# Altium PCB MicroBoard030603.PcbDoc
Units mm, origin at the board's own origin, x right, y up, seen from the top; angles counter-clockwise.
Board outline 99.8 x 61.6 mm, 2 copper layers (Top Layer, Bottom Layer); 74 components, 76 nets, 326 pads, 104 vias.
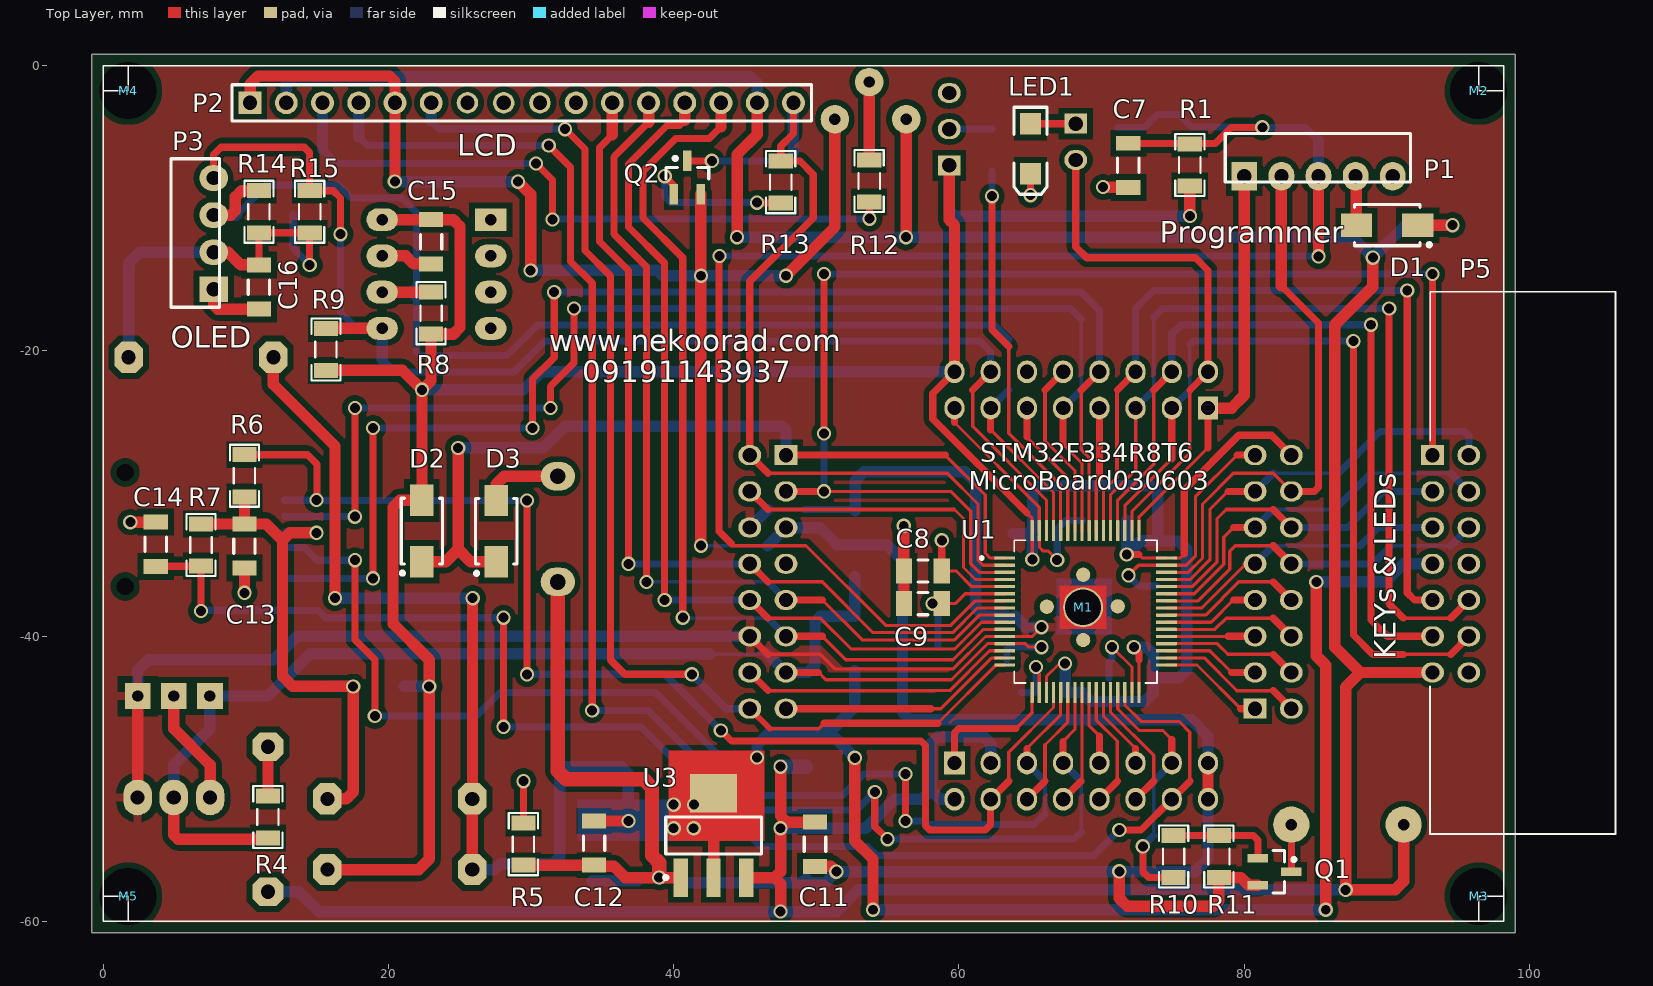
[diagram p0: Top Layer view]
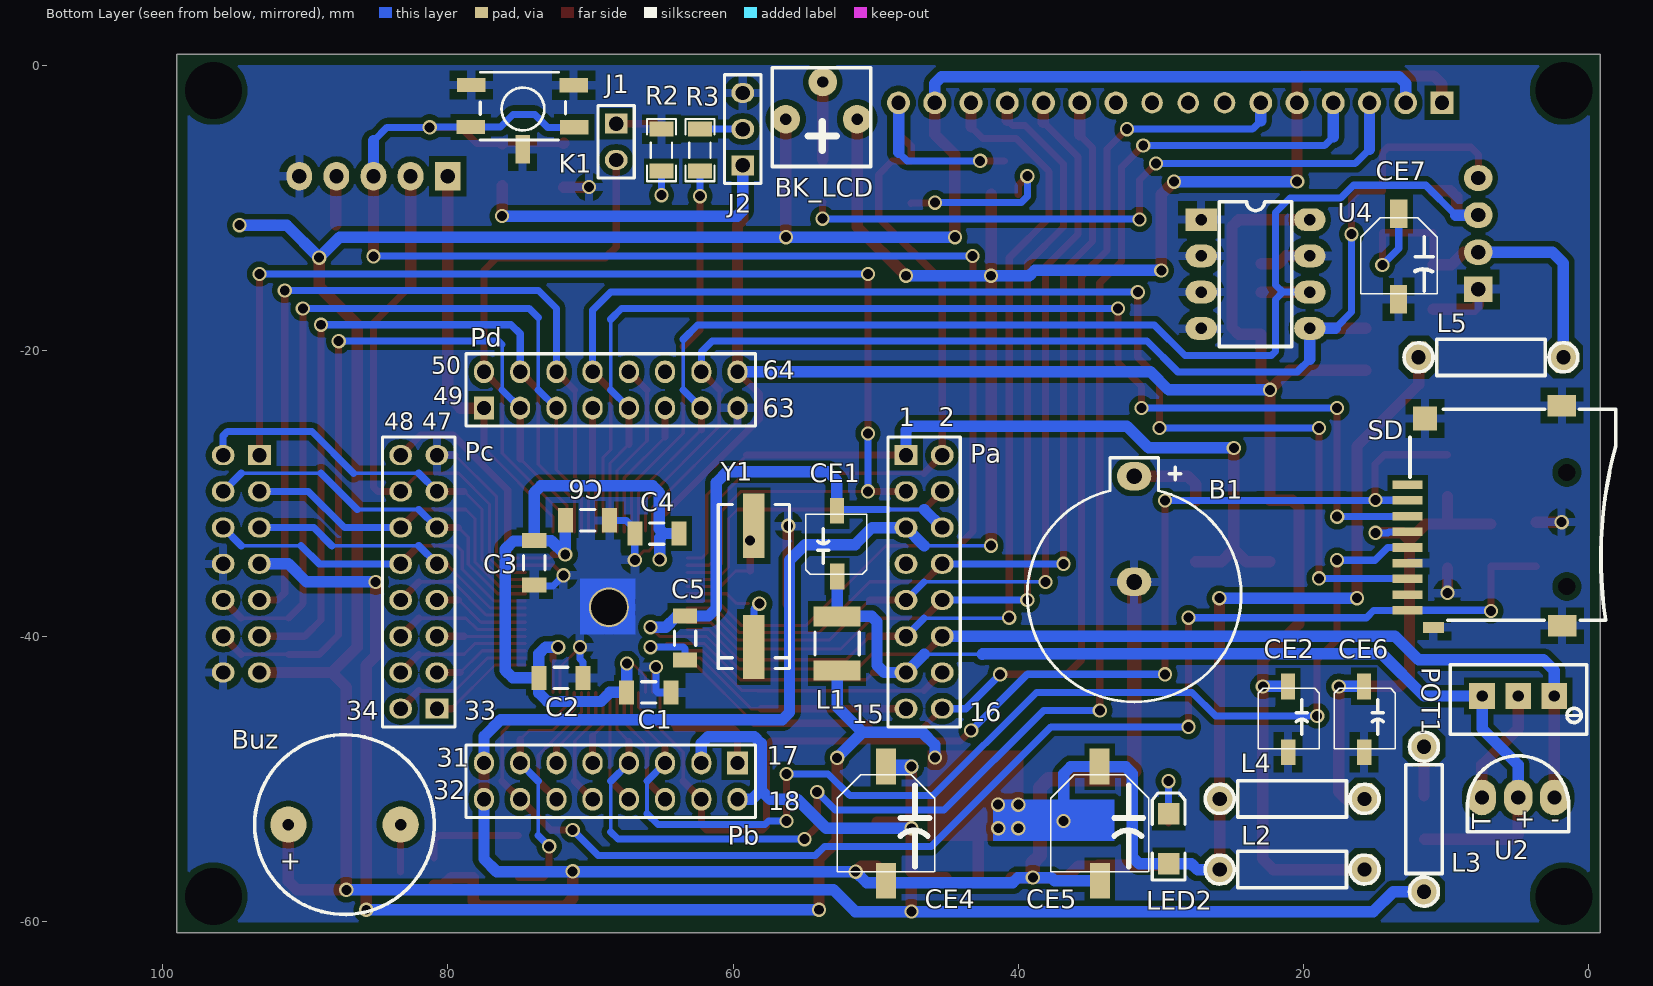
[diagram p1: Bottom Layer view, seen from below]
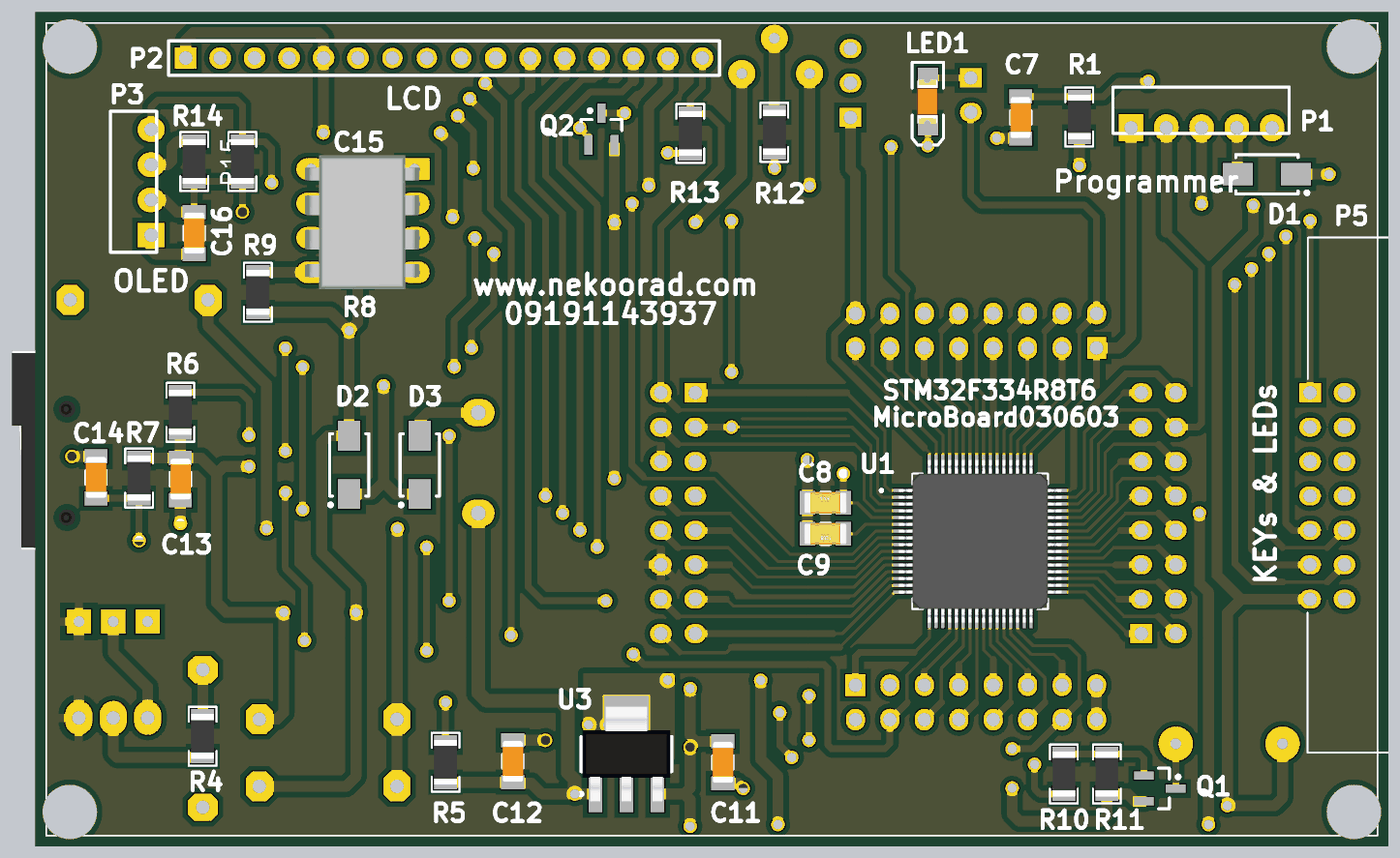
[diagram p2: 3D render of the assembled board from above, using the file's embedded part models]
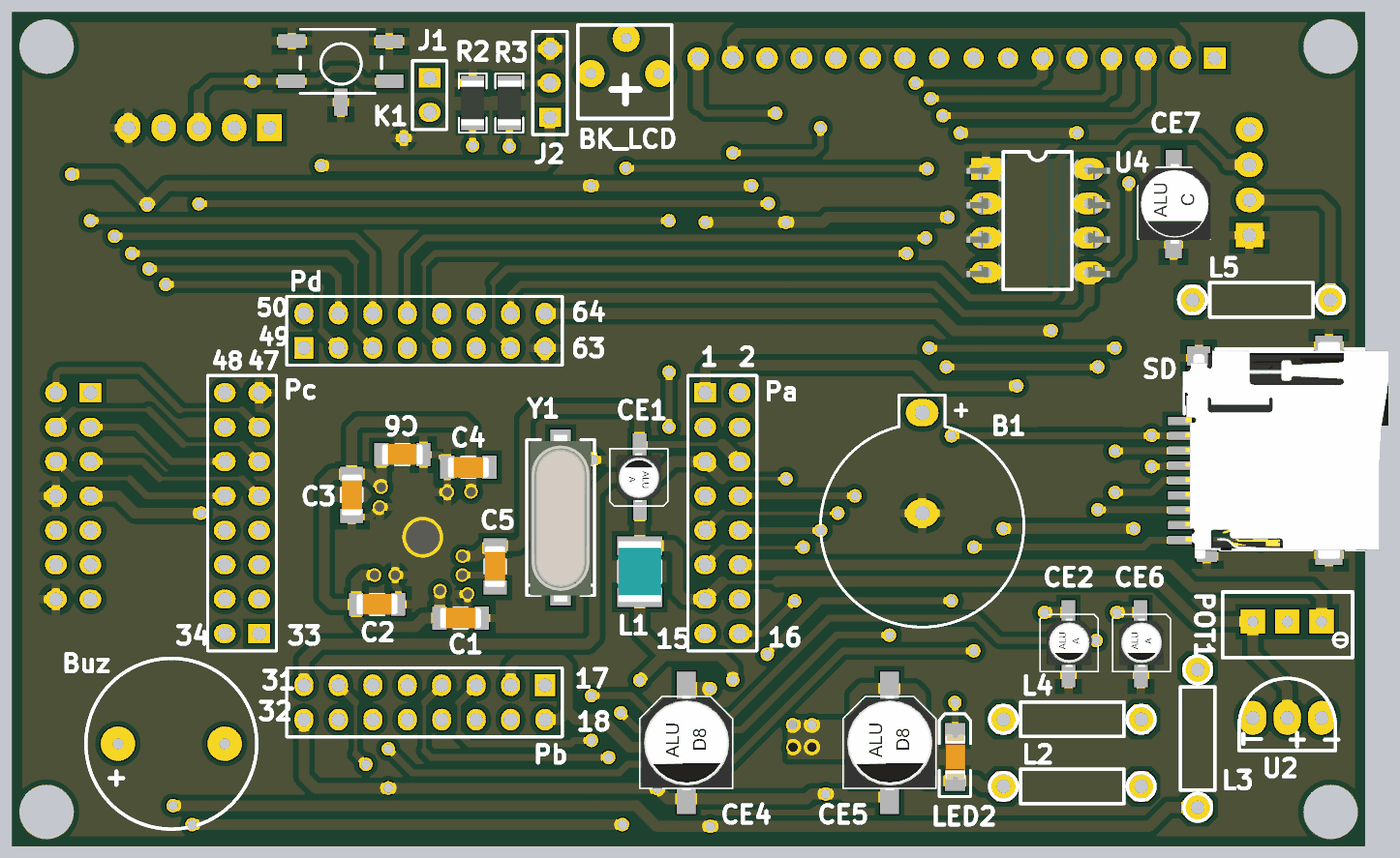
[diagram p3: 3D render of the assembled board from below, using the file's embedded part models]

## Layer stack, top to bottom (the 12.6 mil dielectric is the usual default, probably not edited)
Top Solder: solder mask 0.0102, Solder Resist, Dk 3.5
Top Layer: signal copper 0.0356
Dielectric 1: dielectric 0.32, FR-4, Dk 4.8
Bottom Layer: signal copper 0.0356
Bottom Solder: solder mask 0.0102, Solder Resist, Dk 3.5

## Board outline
-0.8,-60.8 -0.8,0.8 99,0.8 99,-60.8

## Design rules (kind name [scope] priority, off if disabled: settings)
Clearance Clearance_2 [InNamedPolygon('Bottom Layer-GND')] p1: gap=0.254 ignorepadtopadclearanceinfootprint=FALSE except(0: Arc-Hole Track-Hole SMDPad-Hole THPad-Hole Via-Hole Fill-Hole Poly-Hole Region-Hole Text-Hole)
Clearance Clearance_1 [InNamedPolygon('Bottom Layer-GND')] p2: gap=0.254 ignorepadtopadclearanceinfootprint=FALSE except(0: Arc-Hole Track-Hole SMDPad-Hole THPad-Hole Via-Hole Fill-Hole Poly-Hole Region-Hole Text-Hole)
Clearance [All] p3: gap=0.4 ignorepadtopadclearanceinfootprint=FALSE
PlaneClearance [All] p1: clearance=0.5
PlaneConnect [All] p1: planeconnectstyle=Relief reliefexpansion=0.508 reliefentries=4 reliefconductorwidth=0.6 reliefairgap=0.5
PolygonConnect [All] p1: connectstyle=Relief reliefconductorwidth=0.6 reliefentries=4 polygonreliefangle="90 Angle" airgapwidth=0.5
RoutingVias [All] p1: holewidth=0.711 width=1.27 viastyle="Through Hole" minholewidth=0.711 minwidth=1.27 maxholewidth=0.711 maxwidth=1.27
SolderMaskExpansion [All] p1: expansion=0.102 istentingtop=FALSE
Width [All] p1: maxlimit=1 minlimit=0.2 preferedwidth=0.5 minimp=50.000000 maximp=50.000000 favimp=50.000000
28 further rules are at their usual default settings.

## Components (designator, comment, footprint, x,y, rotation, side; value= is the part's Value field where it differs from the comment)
B1 "CR1220 Holder" "BAT S" 31.877,-28.778 r0 bottom
BK_LCD "10K" POT-Blue 56.298,-3.759 r180 bottom
Buz "BUZZER" BUZ 87.249,-53.213 r0 bottom
C1 "Comment" SMD_CAP_1206. 65.913,-43.942 r0 bottom
C2 "Comment" SMD_CAP_1206. 72.068,-42.927 r0 bottom
C3 "Comment" SMD_CAP_1206. 73.946,-34.849 r90 bottom
C4 "Comment" SMD_CAP_1206. 65.346,-32.8 r180 bottom
C5 "Comment" SMD_CAP_1206. 63.373,-40.132 r270 bottom
C6 "Comment" SMD_CAP_1206. 70.206,-31.877 r0 bottom
C7 "Comment" SMD_CAP_1206. 71.882,-6.985 r270 top
C8 "Comment" "CAP 1206 (3216X15L)" 57.476,-35.433 r0 top
C9 "Comment" "CAP 1206 (3216X15L)" 57.476,-37.719 r180 top
C11 "Comment" SMD_CAP_1206. 49.911,-54.585 r90 top
C12 "Comment" SMD_CAP_1206. 34.417,-54.508 r90 top
C13 "Comment" SMD_CAP_1206. 9.906,-33.68 r90 top
C14 "Comment" SMD_CAP_1206. 3.683,-33.553 r90 top
C15 "Comment" SMD_CAP_1206. 22.987,-12.344 r90 top
C16 "Comment" SMD_CAP_1206. 10.922,-15.519 r90 top
CE1 "10uf tantal" cap-e-2 52.795,-32.424 r0 bottom
CE2 "10uf tantal" cap-e-2 21.007,-46.913 r180 bottom
CE4 "100uF" cap-e-4 49.276,-55.44 r180 bottom
CE5 "100uF" cap-e-4 34.29,-55.44 r180 bottom
CE6 "10uf tantal" cap-e-2 15.673,-46.913 r180 bottom
CE7 "47uf tantal" CAP-E-3 13.26,-15.283 r180 bottom
D1 "SS12" "Diode SMA-M" 90.034,-11.176 r180 top
D2 "SS12" "Diode SMA-M" 22.352,-32.63 r90 top
D3 "SS12" "Diode SMA-M" 27.559,-32.639 r90 top
J1 "HDRM2" HDR1X2 68.199,-4.064 r270 bottom
J2 "HDRM3" HDR1X3 59.324,-6.985 r90 bottom
K1 "Push Button" "SW PB SMD" 78.359,-4.318 r180 bottom
L1 "Comment" INDC4532 52.705,-40.508 r270 bottom
L2 "Comment" "L RES" 25.908,-56.388 r180 bottom
L3 "Comment" "L RES" 11.532,-57.937 r90 bottom
L4 "Comment" "L RES" 25.908,-51.435 r180 bottom
L5 "Comment" "L RES" 11.963,-20.472 r180 bottom
LED1 "HB" LED_SMD_1206 62.803,-5.908 r270 top
LED2 "HB" LED_SMD_1206 27.243,-54.107 r90 bottom
M1 "Comment" Stud-hole#1 68.707,-37.973 r0 top value=DNP/MH
M2 "Comment" Stud-hole#2 96.45,-1.75 r0 top value=DNP/MH
M3 "Comment" Stud-hole#2 96.45,-58.25 r0 top value=DNP/MH
M4 "Comment" Stud-hole#2 1.75,-1.75 r0 top value=DNP/MH
M5 "Comment" Stud-hole#3 1.75,-58.25 r0 top value=DNP/MH
P1 "Programmer" "SIP 5 right" 90.431,-7.772 r270 top
P2 "LCD" HDR1X16 10.3,-2.6 r0 top
P3 "OLED" "sip 4 right" 7.747,-7.849 r0 top
P5 "Key LED" "IDC14 r lock" 93.243,-27.305 r270 top
Pa "Header 8X2" HDR2X8#1 47.879,-27.305 r270 bottom
Pb "Header 8X2" HDR2X8#2 59.69,-48.895 r0 bottom
Pc "Header 8X2" HDR2X8#1 80.772,-45.085 r90 bottom
Pd "Header 8X2" HDR2X8#1 77.47,-24.003 r180 bottom
POT1 "10K" "pot multi turn" 2.423,-44.196 r90 bottom
Q1 "BCV47" SOT23_M 82.137,-56.515 r0 top
Q2 "BCV47" SOT23_M 40.96,-7.842 r90 top
R1 "4K7" RES_1206 75.311,-6.985 r270 top
R2 "1K" RES_1206 65.905,-5.956 r270 bottom
R3 "100K" RES_1206 61.443,-5.884 r90 bottom
R4 "220" RES_1206 10.668,-52.705 r270 top
R5 "1K" RES_1206 30.345,-54.547 r90 top
R6 "4K7" RES_1206 9.025,-28.787 r270 top
R7 "10K" RES_1206 5.977,-33.642 r270 top
R8 "4K7" RES_1206 22.106,-17.386 r270 top
R9 "4K7" RES_1206 14.74,-19.926 r270 top
R10 "10K" RES_1206 74.176,-55.486 r270 top
R11 "10K" RES_1206 79.113,-55.414 r90 top
R12 "1K" RES_1206 54.588,-8.043 r90 top
R13 "10K" RES_1206 48.387,-8.128 r90 top
R14 "10K" RES_1206 10.041,-10.274 r270 top
R15 "10K" RES_1206 13.597,-10.274 r270 top
SD "Comment" "Micro sd csrd" 5.051,-31.213 r180 bottom
U1 "STM32F334R8T6" STM32F334R8T6 61.587,-34.522 r0 top
U2 "LM336" LM336 2.413,-51.308 r90 bottom
U3 "Comment" MP04A_M 42.799,-53.975 r90 top value=AMS1117-3.3V
U4 "EEPROM_I2C" dip8 27.178,-10.795 r180 bottom
Y1 "8Mhz" "Crystal SMD" 58.623,-36.234 r180 bottom

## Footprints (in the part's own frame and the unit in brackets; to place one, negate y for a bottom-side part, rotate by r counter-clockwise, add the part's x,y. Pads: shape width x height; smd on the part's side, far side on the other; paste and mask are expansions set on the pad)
"BAT S" [mm]
  oval 2.4x2 hole 1.1: 1(0,0) 2(0,7.417)
  silkscreen extent -7.5,-1.29 7.5,15.83
BUZ [mm]
  round 2.54 hole 0.8: 1(3.937,0) 2(-3.937,0)
  silkscreen extent -6.3,-6.3 6.3,6.3
"CAP 1206 (3216X15L)" [mm] "Chip Capacitor, 2-Leads, Body 3.2x1.6mm, IPC High Density"
  rect 1.15x1.75 smd: 1(-1.325,0) 2(1.325,0)
  silkscreen extent -0.35,-0.77 0.35,0.77, body extent -1.6,-0.8 1.6,0.8, height 1
cap-e-2 [mm] "1u-50v"
  rect 1x1.8 smd: 1(-0.09,3.39) 2(-0.075,-1.22)
  silkscreen extent -2.17,-0.98 2.11,3.25, body extent -1.68,-0.65 1.62,2.95, height 5.4
CAP-E-3 [mm] "22u-35v"
  rect 1.2x2 smd: 1(-0.065,4.9) 2(-0.075,-1.1)
  silkscreen extent -2.72,-0.69 2.62,4.62, body extent -2.64,-1.03 2.66,4.87, height 5.41
cap-e-4 [mm] "(100u-35v)(47u-16v)(220u-16v)(100u-16v)(10u-50v)"
  rect 1.4x2.5 smd: 1(-0.005,6.3) 2(0,-1.71)
  silkscreen extent -3.43,-1.07 3.43,5.71, body extent -3.27,-1.22 3.33,5.78, height 7.7
"Crystal SMD" [mm]
  rect 1.5x4.5 smd: 1(0.076,-4.524) 2(0.076,3.976)
  silkscreen extent -2.42,-6.02 2.58,5.48, body extent -2.17,-6.48 2.33,5.82, height 5.18
"Diode SMA-M" [mm] "Molded Diode, 2-Leads, Body 4.30x2.70mm, IPC Low Density"
  rect 2.2x1.65 smd: 1(2.15,0) 2(-2.15,0)
  silkscreen extent -3.08,-1.45 2.3,1.5, body extent -2.3,-1.45 2.3,1.45, height 2.44
dip8 [mm]
  rect 2.2x1.6 hole 0.8: 1(0,0)
  oval 2.2x1.6 hole 0.8: 2(0,-2.54) 3(0,-5.08) 4(0,-7.62) 5(7.62,-7.62) 6(7.62,-5.08) 7(7.62,-2.54) 8(7.62,0)
  silkscreen extent 1.27,-8.89 6.35,1.27, body extent -1.42,-8.88 9.14,1.02, height 3.75
HDR1X2 [mm] "Connector; Header; 2 Position"
  rect 1.4x1.6 hole 1: 1(0,0)
  oval 1.4x1.6 hole 1: 2(2.54,0)
  silkscreen extent -1.27,-1.27 3.81,1.27
HDR1X3 [mm] "Connector; Header; 3 Position"
  rect 1.4x1.6 hole 1: 1(0,0)
  oval 1.4x1.6 hole 1: 2(2.54,0) 3(5.08,0)
  silkscreen extent -1.27,-1.27 6.35,1.27
HDR1X16 [mm] "Connector; Header; 16 Position"
  rect 1.6x1.6 hole 1: 1(0,0)
  round 1.6 hole 1: 2(2.54,0) 3(5.08,0) 4(7.62,0) 5(10.16,0) 6(12.7,0) 10(22.86,0) 11(25.4,0) 12(27.94,0) 13(30.48,0) 14(33.02,0) 15(35.56,0) 16(38.1,0)
  round 1.5 hole 1: 7(15.24,0) 8(17.78,0) 9(20.32,0)
  silkscreen extent -1.27,-1.27 39.37,1.27
HDR2X8#1 [mm] "Connector; Header; 8x2 Position"
  rect 1.4x1.6 hole 1: 1(0,0)
  oval 1.4x1.6 hole 1: 2(0,2.54) 3(2.54,0) 4(2.54,2.54) 5(5.08,0) 6(5.08,2.54) 7(7.62,0) 8(7.62,2.54) 9(10.16,0) 10(10.16,2.54) 11(12.7,0) 12(12.7,2.54) 13(15.24,0) 14(15.24,2.54) 15(17.78,0) 16(17.78,2.54)
  silkscreen extent -1.27,-1.27 19.05,3.81
HDR2X8#2 [mm] "Connector; Header; 8x2 Position"
  rect 1.5x1.6 hole 1: 1(0,0)
  oval 1.4x1.6 hole 1: 2(0,2.54) 3(2.54,0) 4(2.54,2.54) 5(5.08,0) 6(5.08,2.54) 7(7.62,0) 8(7.62,2.54) 9(10.16,0) 10(10.16,2.54) 11(12.7,0) 12(12.7,2.54) 13(15.24,0) 14(15.24,2.54) 15(17.78,0) 16(17.78,2.54)
  silkscreen extent -1.27,-1.27 19.05,3.81
"IDC14 r lock" [mm]
  rect 1.4x1.6 hole 1: 1(0,-0.025)
  oval 1.4x1.6 hole 1: 2(0,2.515) 3(2.54,-0.025) 4(2.54,2.515) 5(5.08,-0.025) 6(5.08,2.515) 7(7.62,-0.025) 8(7.62,2.515) 9(10.16,-0.025) 10(10.16,2.515) 11(12.7,-0.025) 12(12.7,2.515) 13(15.24,-0.025) 14(15.24,2.515)
  silkscreen extent -11.46,-0.22 26.57,12.81
INDC4532 [mm] "Chip Inductor, Body 4.5x3.2mm, IPC High Density"
  rect 1.4x3.3 smd: 1(-1.9,0) 2(1.9,0)
  silkscreen extent -0.8,-1.55 0.8,1.55, body extent -2.25,-1.6 2.25,1.6, height 1.75
"L RES" [mm]
  oct 2x2.2 hole 1: 1(0.025,0.025) 2(10.185,0.025)
  silkscreen extent -0.99,-1.24 11.2,1.3
LED_SMD_1206 [mm] "SMD"
  rect 1.5x1.5 smd: 1(-1.844,2.221) 2(1.656,2.221)
  silkscreen extent -2.99,1.07 3.11,3.37, body extent -1.74,1.46 1.56,2.91, height 1.36
LM336 [mm]
  oval 2.5x2 hole 1: 1(0,0) 2(0,2.54) 3(0,5.08)
  silkscreen extent -2.41,-1.02 2.92,6.1
"Micro sd csrd" [mm]
  rect 2.1x0.6 smd: 1(-7.649,1.831) 2(-7.649,0.731) 3(-7.649,-0.369) 4(-7.649,-1.469) 5(-7.649,-2.569) 6(-7.649,-3.669) 7(-7.649,-4.769) 8(-7.649,-5.869) 9(-7.649,-6.969)
  rect 1.5x0.8 smd: 10(-5.838,-8.178)
  rect 1.7x1.7 smd: 11(-6.43,6.481)
  rect 2x1.5 smd: 12(3.179,-8.051) 13(3.17,7.381)
  round 0.5 hole 1.2 unplated mask+0.05: ""(3.506,-5.305) ""(3.506,2.696)
  silkscreen extent -7.49,-7.67 6.93,7.13, body extent -7.68,-8.35 7.57,7.65, height 1.85
MP04A_M [mm] "SOT223, 4-Leads, Body 6.5x3.5mm, Pitch 2.3mm, Lead Span 7mm, IPC Low Density"
  rect 2.7x1 smd: 1(-2.95,2.3) 2(-2.95,0) 3(-2.95,-2.3)
  rect 2.7x3.3 smd: 4(2.95,0)
  silkscreen extent -3.07,-3.35 1.3,3.47, body extent -3.49,-3.24 3.49,3.24, height 1.64
"pot multi turn" [mm]
  rect 1.8x1.8 hole 0.8: 1(0,5.06) 2(0,0) 3(0,2.53)
  silkscreen extent -2.67,-2.29 2.18,7.29
POT-Blue [mm]
  round 2 hole 0.8: 1(-0.009,0.013) 2(4.991,0.013) 3(2.591,2.616)
  silkscreen extent -0.97,-3.3 5.94,3.61
RES_1206 [mm] "SMD"
  rect 1.05x1.7 smd: 1(-1.511,0.881) 2(1.439,0.881)
  silkscreen extent -2.21,-0.14 2.14,1.91, body extent -1.69,0.03 1.61,1.73, height 0.94
"sip 4 right" [mm]
  rect 2x1.8 hole 1: 1(0,-7.825)
  oval 2x1.8 hole 1: 2(0,-5.225) 3(0,-2.625) 4(0,-0.025)
  silkscreen extent -3,-9.09 0.41,1.32
"SIP 5 right" [mm]
  rect 2x1.8 hole 1: 1(-0.025,-10.414)
  oval 2x1.8 hole 1: 2(-0.025,-7.814) 3(-0.025,-5.214) 4(-0.025,-2.614) 5(-0.025,-0.014)
  silkscreen extent -3.03,-11.75 0.38,1.25
SMD_CAP_1206. [mm]
  rect 1.05x1.7 smd: 1(-1.549,0) 2(1.549,0)
  silkscreen extent -0.5,-0.75 0.5,0.75, body extent -1.52,-0.77 1.53,0.75, height 0.75
SOT23_M [mm] "SOT23, 3-Leads, Body 2.9x1.3mm, Pitch 0.95mm, Lead Span 2.3mm - Reverse Pinning, IPC Low Density"
  rect 1.45x0.6 smd: 1(-1.175,0.95) 2(-1.175,-0.95) 3(1.175,0)
  silkscreen extent -0.1,-1.5 1.48,1.5, body extent -0.7,-1.5 0.7,1.5, height 1.1
STM32F334R8T6 [mm]
  rrect25% 1.47x0.229 smd: 1(1.629,0) 2(1.629,-0.5) 3(1.629,-1) 4(1.629,-1.5) 5(1.629,-2) 6(1.629,-2.5) 7(1.629,-3) 8(1.629,-3.5) 9(1.629,-4) 10(1.629,-4.5) 11(1.629,-5) 12(1.629,-5.5) 13(1.629,-6) 14(1.629,-6.5) 15(1.629,-7) 16(1.629,-7.5) 33(12.969,-7.5) 34(12.969,-7) 35(12.969,-6.5) 36(12.969,-6) 37(12.969,-5.5) 38(12.969,-5) 39(12.969,-4.5) 40(12.969,-4) 41(12.969,-3.5) 42(12.969,-3) 43(12.969,-2.5) 44(12.969,-2) 45(12.969,-1.5) 46(12.969,-1) 47(12.969,-0.5) 48(12.969,0)
  rrect25% 0.229x1.47 smd: 17(3.549,-9.42) 18(4.049,-9.42) 19(4.549,-9.42) 20(5.049,-9.42) 21(5.549,-9.42) 22(6.049,-9.42) 23(6.549,-9.42) 24(7.049,-9.42) 25(7.549,-9.42) 26(8.049,-9.42) 27(8.549,-9.42) 28(9.049,-9.42) 29(9.549,-9.42) 30(10.049,-9.42) 31(10.549,-9.42) 32(11.049,-9.42) 49(11.049,1.92) 50(10.549,1.92) 51(10.049,1.92) 52(9.549,1.92) 53(9.049,1.92) 54(8.549,1.92) 55(8.049,1.92) 56(7.549,1.92) 57(7.049,1.92) 58(6.549,1.92) 59(6.049,1.92) 60(5.549,1.92) 61(5.049,1.92) 62(4.549,1.92) 63(4.049,1.92) 64(3.549,1.92)
  silkscreen extent -0.08,-8.75 12.3,1.25, body extent 1.3,-9.75 13.3,2.25, height 1.6
Stud-hole#1 [mm]
  round 2.8 hole 2.5: 1(0,0)
Stud-hole#2 [mm]
  round 1.524 hole 4: 1(0,0)
Stud-hole#3 [mm]
  round 1.524 hole 4: ""(0,0)
"SW PB SMD" [mm]
  rect 2x1 smd: 1(-0.005,2.975) 1(7.175,2.95) 2(-0.025,0.02) 2(7.215,0)
  rect 1x2 smd: 3(3.605,-1.545)
  silkscreen extent 0.62,-0.9 6.62,3.85

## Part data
B1: library part "Battry Backup"
BK_LCD POT1: library part POT2
C1 C2 C3 C4 C5 C6 C7 C8 C9 C11 C12 C13 C14 C15 C16: library part "Capacitor SMD"
CE1 CE2 CE4 CE5 CE6 CE7: library part "Capacitor Tantalium"
D1 D2 D3: library part 1N4001
J1: library part HDR_M_1X2, "CONN, HEADER, Male, pitch: 2.54mm, 2POS"
J2: library part HDR_M_1X3, "CONN, HEADER, Male, pitch: 2.54mm, 3POS"
K1: library part "Push Kay"
L1 L2 L3 L4 L5: library part "Ferrit Bead"
LED1 LED2: library part LED, "LED"
M1 M2 M3 M4 M5: library part SCMH_M1P6, "SCREW mouting, M1.6, 1.6mm diameter and 3.2mm PanHead"
P1: library part "Header 5", "Header, 5-Pin"
P2: library part "Header 16", "Header, 16-Pin"
P3: library part "Header 4", "Header, 4-Pin"
P5: library part "Header 7X2", "Header, 7-Pin, Dual row"
Pa Pb Pc Pd: "Header, 8-Pin, Dual row"
Q1 Q2: library part "NPN DAR"
R1 R2 R3 R4 R5 R6 R7 R8 R9 R10 R11 R12 R13 R14 R15: library part Resistor, "Resistor", Power="1/8 W", Tolerance=5%
SD: library part "Micro SD Card"
U1: "No Description Available", Mfr_Name=STMicroelectronics
U3: library part VREG_1117_SOT223, "REG, Linear, LDO1V, 0.8A, SOT-223"
U4: library part AT24C128
Y1: library part Xtal

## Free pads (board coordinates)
  round 1 smd: 6(71.143,-37.906) 7(68.716,-35.694) 8(66.168,-37.931) 9(68.716,-40.269)

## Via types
v1: diameter 1, hole 0.7, Top Layer to Bottom Layer, 104 vias

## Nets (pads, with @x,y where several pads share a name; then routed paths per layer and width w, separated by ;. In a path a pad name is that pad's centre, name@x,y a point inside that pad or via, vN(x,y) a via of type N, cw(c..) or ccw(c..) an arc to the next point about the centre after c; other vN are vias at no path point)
+3V3: C12.2 CE5.1 L1.2 L2.1 L4.1 L5.1 LED2.1 P5.7 U3.2 U3.4 | length 174.5
  Top Layer w0.8: L5.1 11.938,-22.352 16.256,-26.67 v1(16.256,-37.338) ; L2.1 L4.1 25.895,-51.397 v1@25.895,-37.351 ; C12.2 v1(36.83,-52.959) ; U3.2 U3.4 43.099,-51.025 45.61,-48.514 v1(45.847,-48.514) ; v1(52.705,-48.532) 52.705,-54.356 53.975,-55.626 v1(53.975,-59.182) ; v1(85.06,-36.195) 85.06,-41.372 85.725,-42.037 v1(85.725,-59.182)
  Bottom Layer w0.8: v1(16.256,-37.338) v1(25.908,-37.338) ; L2.1@25.883,-56.388 27.432,-56.388 27.869,-55.951 LED2.1 31.535,-55.951 32.004,-55.482 32.004,-49.636 32.473,-49.167 34.095,-49.167 34.122,-49.14 36.313,-49.14 36.83,-49.657 v1(36.83,-52.959) 38.608,-52.959 39.727,-51.84 41.402,-51.84 v1(41.427,-51.816) ; v1(45.847,-48.514) 45.847,-47.625 46.736,-46.736 50.934,-46.736 ; v1(52.705,-48.532) 52.705,-48.507 50.934,-46.736 ; L1.2 52.705,-44.965 50.934,-46.736 ; v1(53.975,-59.182) v1(85.725,-59.182) ; v1(85.06,-36.195) 89.916,-36.195 91.186,-34.925 P5.7
  other v1: 40.005,-53.467 41.402,-53.467 40.005,-51.816
+3V3_MIC: C1.2 C2.2 C3.2 C4.2 C6.2 C15.2 CE2.1 D2.1 J2.1 L2.2 Pc.16 Pd.16 R1.2 R8.2 R9.2 U1.19 U1.32 U1.48 U1.64 U4.8 | length 236.8
  Top Layer w0.22: 64.77,-31.369 65.136,-31.735 U1.64 ; v1@65.141,-34.63 U1.64@65.141,-32.607 ; U1.19 66.136,-42.83 67.056,-41.91 v1(67.437,-41.91) ; 72.629,-34.275 72.876,-34.522 U1.48 ; U1.32@72.64,-43.938 72.64,-41.655 ; U1.48@75.041,-34.522 75.506,-34.522 75.799,-34.229
  Top Layer w0.5: Pd.16 58.166,-22.987 58.166,-24.765 64.77,-31.369 ; v1(71.771,-34.275) 72.629,-34.275 ; v1(72.263,-40.767) 72.64,-41.144 72.64,-41.655 ; 75.799,-34.229 75.799,-29.738 79.629,-25.908 81.915,-25.908 Pc.16
  Top Layer w0.8: R9.2 20.984,-21.365 22.345,-22.726 v1(22.352,-22.726) ; L2.2 22.123,-56.363 22.86,-55.626 v1(22.86,-43.523) 22.86,-41.656 20.32,-39.116 20.32,-30.949 20.789,-30.48 D2.1 22.352,-22.733 22.987,-22.098 R8.2 24.55,-18.825 25.019,-18.356 25.019,-11.264 24.55,-10.795 C15.2 U4.8 ; J2.1 59.324,-10.81 59.69,-11.176 Pd.16 ; v1(76.2,-10.541) 76.196,-10.537 76.196,-8.424 R1.2@76.2,-8.42
  Bottom Layer w0.8: CE2.1 v1(22.86,-43.523) ; v1(22.352,-22.726) 22.359,-22.733 29.464,-22.733 30.734,-21.463 Pd.16 ; J2.1 59.324,-10.16 59.705,-10.541 v1(76.2,-10.541) ; C4.2 64.853,-32.8 ; v1(65.146,-34.625) 65.146,-33.093 64.853,-32.8 ; v1(67.437,-41.91) 67.45,-41.923 67.45,-43.929 C1.2 68.638,-43.942 69.273,-44.577 69.661,-44.577 ; 69.662,-44.577 73.023,-44.577 73.617,-43.983 C2.2 ; C6.2 71.763,-31.885 v1@71.763,-34.267 ; v1(71.771,-34.275) 72.746,-33.3 C3.2 ; v1(72.263,-40.767) 73.152,-40.767 73.617,-41.232 C2.2 ; 64.853,-32.8 65.171,-32.482 65.171,-29.933 65.64,-29.464 73.477,-29.464 73.946,-29.933 C3.2 ; C2.2 75.444,-42.927 75.971,-42.4 75.971,-33.9 75.396,-33.325 73.971,-33.325 C3.2
+3V3_OLED: C16.2 CE7.1 L5.2 P3.2 R14.2 R15.2 | length 28.7
  Top Layer w0.5: P3.2@7.627,-12.954 P3.2 P3.2@7.751,-13.077 ; 10.919,-13.077 10.922,-13.081 ; C16.2 10.922,-13.081 ; v1(14.478,-13.97) R15.2 R14.2 10.922,-13.081
  Top Layer w0.8: P3.2@7.751,-13.077 8.76,-13.077 9.649,-13.966 C16.2@10.919,-13.966
  Bottom Layer w0.5: CE7.1 13.325,-12.817 v1(14.478,-13.97)
  Bottom Layer w0.8: L5.2 1.778,-13.843 2.547,-13.074 P3.2
+3V3_SD: C13.2 CE6.1 L4.2 R6.2 R7.1 SD.4 | length 38.9
  Top Layer w0.8: R7.1 C13.2 ; R6.2 C13.2 ; v1(14.956,-32.752) 13.095,-32.752 12.573,-33.274 ; L4.2 17.043,-51.41 17.526,-50.927 v1(17.526,-43.523) 13.297,-43.523 12.573,-42.799 12.573,-33.274 ; C13.2 11.43,-32.131 12.573,-33.274
  Bottom Layer w0.5: SD.4 14.013,-32.682 14.084,-32.752 v1(14.956,-32.752)
  Bottom Layer w0.8: CE6.1 v1(17.526,-43.523)
+5V0: BK_LCD.1 Buz.1 C11.2 CE4.1 D1.2 L3.1 P2.2 P2.15 P5.13 Pb.2 Pb.3 U3.3 | length 284.7
  Top Layer w0.8: v1(44.45,-12.025) 44.45,-6.225 45.86,-4.815 P2.15 ; U3.3 47.078,-56.925 ; v1(47.498,-59.309) 47.498,-57.345 47.078,-56.925 ; v1(47.498,-49.149) 47.498,-52.603 47.93,-53.035 ; C11.2 47.93,-53.035 ; v1@56.307,-12.011 BK_LCD.1 ; v1(89.027,-13.455) 89.027,-15.494 86.36,-18.161 86.36,-40.767 88.138,-42.545 ; Buz.1 91.186,-57.189 90.59,-57.785 v1(87.122,-57.785) 87.122,-43.561 88.138,-42.545 ; D1.2 v1(94.615,-11.176) ; P5.13 88.138,-42.545 ; 47.078,-56.925 47.498,-56.505 v1(47.498,-53.467) 47.93,-53.035
  Bottom Layer w0.8: L3.1 13.716,-57.912 15.113,-59.309 v1(47.498,-59.309) 51.435,-59.309 52.959,-57.785 v1(87.122,-57.785) ; P2.2 12.84,-1.244 13.309,-0.775 45.391,-0.775 45.86,-1.244 P2.15 ; v1(44.45,-12.025) v1(56.3,-12.025) 87.597,-12.025 v1(89.027,-13.455) ; v1(47.498,-53.467) 53.467,-53.467 55.499,-51.435 57.404,-51.435 58.039,-50.8 ; Pb.2 58.674,-51.435 58.039,-50.8 ; Pb.3 62.23,-47.516 61.761,-47.047 58.508,-47.047 58.039,-47.516 58.039,-50.8 ; v1@89.027,-13.462 91.313,-11.176 v1(94.615,-11.176)
  Bottom Layer w1: v1(47.498,-49.149) 49.272,-49.149 CE4.1
AGND: C5.1 CE1.2 Pa.6 Pa.12 POT1.2 U1.12 U2.1 | length 107.8
  Top Layer w0.22: 50.292,-41.275 51.308,-42.291 59.598,-42.291 61.867,-40.022 U1.12 65.134,-40.022 v1(65.786,-39.37)
  Top Layer w0.25: 46.609,-41.275 50.292,-41.275
  Top Layer w0.5: Pa.12 46.609,-41.275
  Top Layer w0.8: U2.1 POT1.2@2.413,-44.206
  Bottom Layer w0.25: 46.609,-31.115 49.149,-31.115
  Bottom Layer w0.5: 49.149,-31.115 52.631,-31.115 CE1.2
  Bottom Layer w0.8: POT1.2 2.423,-42.408 3.175,-41.656 11.938,-41.656 13.589,-40.005 Pa.12 ; Pa.6 46.609,-31.115 ; CE1.2 52.72,-29.101 53.346,-28.475 60.421,-28.475 61.171,-29.225 61.171,-38.025 61.729,-38.583 C5.1 ; C5.1@63.965,-38.609 64.726,-39.37 v1(65.786,-39.37)
BKL: P2.16 Pa.2 Q2.3 R13.2 U1.2 | length 63.2
  Top Layer w0.22: 59.182,-28.575 61.341,-30.734 61.341,-34.671 61.692,-35.022 U1.2
  Top Layer w0.25: 46.609,-28.575 59.182,-28.575
  Top Layer w0.5: Q2.3 v1(42.672,-6.667) ; 46.609,-28.575 Pa.2 45.339,-15.113 49.784,-10.668 49.784,-7.62 48.853,-6.689 R13.2 47.506,-5.644 48.4,-4.75 P2.16
  Bottom Layer w0.5: v1(42.672,-6.667) 47.808,-6.667 48.4,-6.075
  Bottom Layer w0.8: 48.4,-6.075 P2.16
BOOT0: R3.1 U1.60 | length 27.3
  Top Layer w0.22: 63.5,-25.781 67.131,-29.412 U1.60@67.131,-32.683
  Top Layer w0.25: 63.5,-25.781 63.5,-19.685
  Top Layer w0.5: v1(62.324,-9.144) 62.324,-18.509 63.5,-19.685
  Bottom Layer w0.5: v1(62.324,-9.144) R3.1
Buzzer: Pb.13 R10.2 U1.29 | length 18.3
  Top Layer w0.22: U1.29 71.136,-45.101 72.644,-46.609 74.295,-46.609 74.93,-47.244
  Top Layer w0.5: v1(72.898,-54.737) 72.898,-56.515 73.308,-56.925 R10.2 ; Pb.13 74.93,-47.244
  Bottom Layer w0.25: 73.66,-53.975 73.66,-50.165
  Bottom Layer w0.5: v1(72.898,-54.737) 73.66,-53.975 ; 73.66,-50.165 Pb.13
EN: P2.6 Pa.16 U1.16 | length 80.9
  Top Layer w0.22: 58.532,-46.086 62.581,-42.037 63.202,-42.037 U1.16
  Top Layer w0.25: 46.736,-46.482 50.165,-46.482 50.546,-46.101
  Top Layer w0.4: Pa.16 46.736,-46.482
  Top Layer w0.5: v1(32.385,-4.445) 33.782,-5.842 33.782,-12.954 35.56,-14.732 35.56,-41.656 36.576,-42.672 v1(41.275,-42.672) ; 50.546,-46.101 58.532,-46.101
  Bottom Layer w0.5: 23,-3.875 23.57,-4.445 v1(32.385,-4.445) ; v1(41.275,-42.672) 43.688,-45.085 Pa.16
  Bottom Layer w0.8: 23,-3.875 P2.6
GND: B1.2 C1.1 C2.1 C3.1 C4.1 C6.1 C7.2 C8.1 C9.2 C13.1 C14.2 C15.1 C16.1 CE2.2 CE6.2 CE7.2 J2.3 K1.1 K1.3 M1.1 P1.5 P3.1 P5.8 P5.14 Pc.15 Pd.15 R2.1 SD.6 SD.10 SD.11 SD.12 SD.13 U1.18 U1.31 U1.47 U1.63 U4.1 U4.2 U4.3 U4.4 U4.7 | length 88.5
  Top Layer w0.22: 59.69,-25.019 65.636,-30.965 U1.63 65.651,-32.617 65.651,-33.773 65.913,-34.036 66.282,-34.036 v1(66.896,-34.65) ; v1(65.405,-42.164) 65.405,-42.38 65.636,-42.611 U1.18 ; v1(70.739,-40.767) 72.136,-42.164 U1.31 ; 72.599,-35.022 U1.47 75.941,-35.022 76.581,-34.382 76.581,-30.226 79.502,-27.305
  Top Layer w0.25: v1(71.891,-35.73) 72.599,-35.022
  Top Layer w0.5: 59.69,-25.019 Pd.15 ; C7.2@71.869,-8.522 C7.2 ; 79.502,-27.305 Pc.15
  Top Layer w0.8: v1(1.905,-32.004) C14.2 ; P3.1 7.747,-16.776 8.04,-17.069 C16.1 ; v1(9.906,-36.957) C13.1 ; U4.7 21.209,-13.335 21.768,-13.894 C15.1 ; v1(56.134,-32.258) 56.143,-32.266 56.143,-35.424 C8.1 C9.2 ; v1@70.136,-8.522 C7.2@71.869,-8.522
  Top Layer w1: B1.2 31.877,-49.452 32.463,-50.038 37.895,-50.038 38.481,-50.624 38.481,-54.102
  Bottom Layer w0.22: C3.1@73.87,-36.475 C3.1
  Bottom Layer w0.5: C1.1 65.288,-43.942 65.405,-43.825 v1(65.405,-42.164) ; v1@66.896,-34.65 C4.1 ; C4.1 66.895,-32.475 67.493,-31.877 C6.1 ; C2.1 70.518,-41.828 70.739,-41.607 v1(70.739,-40.767) ; v1(71.891,-35.73) 72.635,-36.475 C3.1@73.87,-36.475
  other v1: 70.104,-8.509
I2C1-SCL: P3.3 Pd.13 R8.1 R14.1 U1.61 U4.6 | length 94.6
  Top Layer w0.22: 62.23,-25.527 66.631,-29.928 U1.61@66.631,-32.683
  Top Layer w0.5: 62.23,-25.527 Pd.13
  Top Layer w0.8: P3.3 8.957,-10.474 9.271,-10.16 9.271,-9.2 9.708,-8.763 R14.1 ; U4.6 R8.1
  Bottom Layer w0.25: 63.5,-22.733 63.5,-19.177
  Bottom Layer w0.5: 9.338,-10.474 11.43,-8.382 16.51,-8.382 17.399,-9.271 20.955,-9.271 21.971,-10.287 21.971,-15.367 21.463,-15.875 ; U4.6 21.463,-15.875 ; Pd.13 63.5,-22.733 ; 63.5,-19.177 62.498,-18.175 30.466,-18.175 28.321,-20.32 22.264,-20.32 21.971,-20.027 21.971,-16.383 21.463,-15.875
  Bottom Layer w0.8: P3.3 9.338,-10.474
I2C1-SDA: P3.4 Pd.14 R9.1 R15.1 U1.62 U4.5 | length 90.7
  Top Layer w0.22: 60.96,-25.273 66.136,-30.449 U1.62
  Top Layer w0.25: 60.96,-25.273 60.96,-22.733
  Top Layer w0.5: P3.4 7.747,-6.223 8.255,-5.715 14.097,-5.715 14.478,-6.096 R15.1 16.129,-8.763 16.637,-9.271 v1(16.637,-11.811) ; 60.96,-22.733 Pd.14
  Top Layer w0.8: R9.1 U4.5
  Bottom Layer w0.5: v1(16.637,-11.811) 16.637,-17.272 17.78,-18.415 ; 19.558,-20.574 20.447,-21.463 28.829,-21.463 30.988,-19.304 61.468,-19.304 62.23,-20.066 Pd.14
  Bottom Layer w0.8: 17.78,-18.415 U4.5 19.558,-20.574
K-R-A: P5.5 Pc.9 U1.41 | length 21
  Top Layer w0.22: U1.41 77.04,-38.022 Pc.9@80.137,-34.925
  Top Layer w0.5: Pc.9@80.137,-34.925 Pc.9
  Bottom Layer w0.25: 82.042,-33.655 88.138,-33.655
  Bottom Layer w0.5: Pc.9 82.042,-33.655 ; 88.138,-33.655 89.408,-32.385 P5.5
K-R-B: P5.6 Pc.10 U1.42 | length 24.7
  Top Layer w0.22: U1.42 76.778,-37.522 78.994,-35.306 78.994,-34.036 79.375,-33.655
  Top Layer w0.25: 79.375,-33.655 82.042,-33.655
  Top Layer w0.5: 82.042,-33.655 Pc.10
  Bottom Layer w0.25: 90.297,-33.655 94.488,-33.655
  Bottom Layer w0.5: Pc.10@83.693,-34.925 89.027,-34.925 90.297,-33.655 ; 94.488,-33.655 P5.6
KEY3-R: P5.4 Pc.11 U1.43 | length 26.3
  Top Layer w0.22: U1.43 76.509,-37.022 78.574,-34.957 78.574,-33.059 79.248,-32.385
  Top Layer w0.5: 79.248,-32.385 Pc.11
  Bottom Layer w0.25: 82.042,-31.115 86.36,-31.115 ; 88.9,-28.575 94.488,-28.575
  Bottom Layer w0.5: Pc.11 82.042,-31.115 ; 86.36,-31.115 88.9,-28.575 ; 94.488,-28.575 P5.4
KEY4: P5.3 Pc.12 U1.44 | length 23.9
  Top Layer w0.22: U1.44 76.367,-36.522 78.105,-34.784 78.105,-31.75 78.74,-31.115
  Top Layer w0.25: 78.74,-31.115 82.042,-31.115
  Top Layer w0.5: 82.042,-31.115 Pc.12
  Bottom Layer w0.5: Pc.12@83.693,-32.385 87.249,-32.385 89.789,-29.845 P5.3
KEY5: P5.2 Pc.13 U1.45 | length 29
  Top Layer w0.22: U1.45 76.225,-36.022 77.597,-34.65 77.597,-31.115 78.867,-29.845
  Top Layer w0.5: 78.867,-29.845 Pc.13
  Bottom Layer w0.25: 82.042,-28.575 86.614,-28.575
  Bottom Layer w0.5: Pc.13 82.042,-28.575 ; 86.614,-28.575 89.535,-25.654 95.465,-25.654 95.758,-25.947 P5.2
KEY6: P5.1 Pa.3 U1.3 | length 90.5
  Top Layer w0.22: v1(50.546,-29.845) 59.436,-29.845 60.833,-31.242 60.833,-34.925 61.43,-35.522 U1.3
  Top Layer w0.5: Pa.3 v1(50.546,-29.845) ; v1(50.546,-25.781) v1(50.546,-14.605) ; P5.1 v1(93.218,-14.605)
  Bottom Layer w0.5: v1(50.546,-29.845) v1(50.546,-25.781) ; v1(50.546,-14.605) v1(93.218,-14.605)
LCD-D4: P2.11 Pa.8 U1.8 | length 62.6
  Top Layer w0.22: 50.419,-36.195 53.975,-39.751 59.57,-39.751 61.299,-38.022 U1.8
  Top Layer w0.25: 46.609,-36.195 50.419,-36.195
  Top Layer w0.5: 35.7,-4.85 34.798,-5.752 34.798,-12.319 36.83,-14.351 v1(36.83,-34.925) ; Pa.8 46.609,-36.195
  Top Layer w0.8: 35.7,-4.85 P2.11
  Bottom Layer w0.5: v1(36.83,-34.925) Pa.8
LCD-D5: P2.12 Pa.9 U1.9 | length 63.1
  Top Layer w0.22: 50.419,-37.465 53.213,-40.259 59.704,-40.259 61.441,-38.522 U1.9
  Top Layer w0.5: v1(38.1,-36.195) 38.1,-14.097 35.814,-11.811 35.814,-6.386 38.24,-3.96 ; Pa.9 50.419,-37.465
  Top Layer w0.8: 38.24,-3.96 P2.12
  Bottom Layer w0.25: v1(38.1,-36.195) 46.609,-36.195
  Bottom Layer w0.5: 46.609,-36.195 Pa.9
LCD-D6: P2.13 Pa.10 U1.10 | length 64.1
  Top Layer w0.22: 50.292,-38.735 52.451,-40.894 59.711,-40.894 61.583,-39.022 U1.10
  Top Layer w0.25: 46.609,-38.735 50.292,-38.735
  Top Layer w0.5: v1(39.37,-37.465) 39.37,-13.843 36.83,-11.303 36.83,-6.895 39.54,-4.185 40.415,-4.185 40.78,-3.82 ; Pa.10 46.609,-38.735
  Top Layer w0.8: 40.78,-3.82 P2.13
  Bottom Layer w0.5: v1(39.37,-37.465) Pa.10
LCD-D7: P2.14 Pa.11 U1.11 | length 65.5
  Top Layer w0.22: 50.419,-40.005 52.07,-41.656 59.591,-41.656 61.725,-39.522 U1.11
  Top Layer w0.5: v1(40.64,-38.705) 40.64,-13.462 37.846,-10.668 37.846,-7.404 40.15,-5.1 42.5,-5.1 43.32,-4.28 ; Pa.11 50.419,-40.005
  Top Layer w0.8: 43.32,-4.28 P2.14
  Bottom Layer w0.25: v1@40.67,-38.735 46.609,-38.735
  Bottom Layer w0.5: 46.609,-38.735 Pa.11
LED1: P5.12 Pd.3 U1.51 | length 56.3
  Top Layer w0.22: U1.51 71.636,-30.853 74.93,-27.559
  Top Layer w0.25: 91.186,-41.275 94.488,-41.275
  Top Layer w0.5: 74.93,-27.559 Pd.3 ; v1(87.66,-19.311) 87.66,-39.908 89.027,-41.275 91.186,-41.275 ; 94.488,-41.275 P5.12
  Bottom Layer w0.25: 76.2,-22.733 76.2,-19.558
  Bottom Layer w0.5: Pd.3 76.2,-22.733 ; 76.2,-19.558 76.447,-19.311 v1(87.66,-19.311)
LED2: P5.11 Pd.4 U1.52 | length 55.2
  Top Layer w0.22: U1.52@71.131,-32.683 71.131,-30.469 73.66,-27.94
  Top Layer w0.25: 73.66,-27.94 73.66,-22.733
  Top Layer w0.5: 73.66,-22.733 Pd.4 ; v1(88.9,-18.161) 88.9,-38.862 90.043,-40.005 P5.11
  Bottom Layer w0.5: Pd.4 74.93,-18.796 75.565,-18.161 v1(88.9,-18.161)
LED3: P5.10 Pd.5 U1.53 | length 60.3
  Top Layer w0.22: U1.53@70.631,-32.683 70.631,-30.08 72.39,-28.321
  Top Layer w0.25: 72.39,-28.321 Pd.5 ; 91.186,-38.735 94.488,-38.735
  Top Layer w0.5: v1(90.17,-17.018) 90.17,-37.719 91.186,-38.735 ; 94.488,-38.735 P5.10
  Bottom Layer w0.25: 73.66,-22.733 73.66,-17.653
  Bottom Layer w0.5: Pd.5 73.66,-22.733 ; 73.66,-17.653 74.302,-17.011 v1@90.163,-17.011
LED4: P5.9 Pd.6 U1.54 | length 59.4
  Top Layer w0.22: U1.54@70.131,-32.683 70.131,-29.818 71.087,-28.862
  Top Layer w0.25: 71.087,-28.862 71.087,-22.766 71.12,-22.733
  Top Layer w0.5: 71.12,-22.733 Pd.6 ; v1(91.44,-15.755) 91.44,-36.957 91.948,-37.465 P5.9
  Bottom Layer w0.5: Pd.6 72.39,-17.018 73.653,-15.755 v1(91.44,-15.755)
MCU_RESET: C7.1 K1.2 P1.3 R1.1 U1.7 | length 118.1
  Top Layer w0.22: 44.044,-33.655 43.965,-33.576 43.965,-33.505 44.044,-33.505 ; 49.276,-33.655 54.864,-39.243 59.436,-39.243 61.157,-37.522 U1.7
  Top Layer w0.25: 44.044,-33.655 49.276,-33.655
  Top Layer w0.5: v1@43.18,-13.365 43.18,-32.641 44.044,-33.505 ; C7.1@71.901,-5.455 R1.1@76.173,-5.455 ; R1.1@76.205,-5.461 77.978,-5.461 79.121,-4.318 v1(81.28,-4.318)
  Top Layer w0.8: C7.1 C7.1@71.901,-5.455 ; R1.1@76.173,-5.455 R1.1 R1.1@76.205,-5.461 ; v1(85.217,-13.365) P1.3
  Bottom Layer w0.5: v1@43.225,-13.35 85.202,-13.35 v1(85.217,-13.365) ; K1.2@71.144,-4.318 73.025,-4.318 73.914,-3.429 75.438,-3.429 76.307,-4.298 K1.2@78.384,-4.298 ; K1.2@78.394,-4.308 v1@81.27,-4.308 ; v1(81.28,-4.318) 84.268,-4.318 85.217,-5.267
  Bottom Layer w0.8: P1.3 85.217,-5.267
  other v1: 43.21,-13.335
NetB1_1: B1.1 D3.1 | length 5.7
  Top Layer w0.8: D3.1 27.559,-29.337 28.118,-28.778 B1.1
NetBK_LCD_3: BK_LCD.3 R12.2 | length 5.5
  Top Layer w0.8: R12.2 BK_LCD.3
NetBuz_2: Buz.2 Q1.3 | length 3.3
  Top Layer w0.5: Q1.3 Buz.2
NetD1_1: D1.1 P1.4 | length 3.5
  Top Layer w0.5: D1.1@87.817,-11.109 87.851,-11.142 D1.1
  Top Layer w0.8: P1.4 87.851,-7.781 D1.1@87.851,-11.142
NetJ1_1: J1.1 LED1.1 | length 3.2
  Top Layer w0.5: LED1.1 J1.1
NetJ2_2: J2.2 R3.2 | length 3
  Bottom Layer w0.5: J2.2 R3.2
NetL3_2: L3.2 R4.1 | length 3.4
  Top Layer w0.8: R4.1@11.557,-51.194 L3.2
NetLED1_2: LED1.2 R2.2 | length 3.1
  Top Layer w0.5: v1@65.024,-9.017 LED1.2
  Bottom Layer w0.5: v1(65.024,-9.073) R2.2
NetLED2_2: LED2.2 R5.2 | length 5.2
  Top Layer w0.5: R5.2 v1(29.464,-50.165)
  Bottom Layer w0.5: LED2.2 v1(29.464,-50.165)
NetPOT1_3: POT1.3 U2.3 | length 8.2
  Top Layer w0.8: POT1.3 4.953,-46.482 7.493,-49.022 U2.3
NetQ1_1: Q1.1 R10.1 R11.2 | length 7.3
  Top Layer w0.5: R10.1 R11.2 80.645,-53.975 80.962,-54.292 Q1.1
NetQ2_1: Q2.1 R13.1 | length 11.3
  Top Layer w0.5: v1(39.37,-7.747) 40.01,-8.387 Q2.1 ; v1@45.867,-9.62 47.487,-9.62 R13.1
  Bottom Layer w0.5: v1(39.37,-7.747) 39.37,-9.17 39.8,-9.6 v1(45.847,-9.6)
OSC_IN: C8.2 U1.5 Y1.2 | length 6.9
  Top Layer w0.22: C8.2@58.928,-35.433 59.817,-35.433 60.906,-36.522 U1.5
  Top Layer w0.5: C8.2 v1(58.801,-33.274)
OSC_OUT: C9.1 U1.6 Y1.1 | length 7.8
  Top Layer w0.22: C9.1@58.928,-37.719 59.737,-37.719 60.434,-37.022 U1.6
  Bottom Layer w0.5: v1(58.166,-37.719) 58.547,-38.1 Y1.1
PA0: Pa.14 U1.14 | length 19.6
  Top Layer w0.22: 58.293,-43.815 59.358,-43.815 62.151,-41.022 U1.14
  Top Layer w0.25: 46.609,-43.815 58.293,-43.815
  Top Layer w0.5: Pa.14 46.609,-43.815
PA1: Pa.15 U1.15 | length 16.8
  Top Layer w0.22: 58.039,-45.085 58.73,-45.085 62.279,-41.537 63.202,-41.537 U1.15
  Top Layer w0.5: Pa.15 58.039,-45.085
PA3: Pb.1 U1.17 | length 9.6
  Top Layer w0.22: 65.136,-45.354 U1.17
  Top Layer w0.25: 64.008,-46.482 65.136,-45.354
  Top Layer w0.5: Pb.1 59.69,-46.775 59.983,-46.482 64.008,-46.482
PA6: Pb.6 U1.22 | length 8.7
  Top Layer w0.22: 66.04,-47.625 67.636,-46.029 U1.22
  Top Layer w0.25: 66.04,-50.165 66.04,-47.625
  Top Layer w0.5: Pb.6 66.04,-50.165
PA15: J1.2 Pd.2 U1.50 | length 36.5
  Top Layer w0.22: U1.50 72.136,-31.242 76.2,-27.178
  Top Layer w0.25: 76.2,-27.178 76.2,-22.733
  Top Layer w0.5: J1.2 68.199,-12.7 68.961,-13.462 76.581,-13.462 77.47,-14.351 Pd.2 76.2,-22.733
PB0: Pb.10 U1.26 | length 8.6
  Top Layer w0.22: U1.26 69.636,-45.887 71.12,-47.371
  Top Layer w0.25: 71.12,-50.165 71.12,-47.371
  Top Layer w0.5: Pb.10 71.12,-50.165
PB1: Pb.11 U1.27 | length 5.9
  Top Layer w0.22: U1.27 70.136,-45.625 72.39,-47.879
  Top Layer w0.5: Pb.11 72.39,-47.879
PB2: Pb.12 U1.28 | length 9.3
  Top Layer w0.22: U1.28 70.636,-45.333 73.66,-48.357 73.66,-48.387
  Top Layer w0.25: 73.66,-50.165 73.66,-48.387
  Top Layer w0.5: Pb.12 73.66,-50.165
PB3: Pd.7 U1.55 | length 8.8
  Top Layer w0.22: U1.55@69.632,-32.683 U1.55@69.632,-31.92 ; U1.55@69.631,-31.92 69.631,-29.175 69.85,-28.956
  Top Layer w0.5: 69.85,-28.956 Pd.7
PB6: Pd.10 U1.58 | length 12.6
  Top Layer w0.22: 66.04,-26.289 68.131,-28.38 U1.58@68.131,-32.683
  Top Layer w0.25: 66.04,-26.289 66.04,-22.733
  Top Layer w0.5: 66.04,-22.733 Pd.10
PB7: Pd.11 U1.59 | length 9.9
  Top Layer w0.22: 64.77,-26.035 67.631,-28.896 U1.59@67.631,-32.683
  Top Layer w0.5: 64.77,-26.035 Pd.11
PB11: C14.1 Pb.14 R7.2 SD.9 U1.30 | length 99.2
  Top Layer w0.22: U1.30@71.651,-43.867 71.651,-44.846 72.778,-45.974 75.438,-45.974 76.2,-46.736
  Top Layer w0.25: 76.2,-50.165 76.2,-46.736
  Top Layer w0.5: C14.1 3.694,-35.092 6.847,-35.092 R7.2 v1(6.858,-38.227) ; v1(28.067,-46.355) v1(28.067,-38.705) ; v1(71.247,-53.594) 72.771,-53.594 Pb.14 76.2,-50.165
  Bottom Layer w0.5: v1(6.858,-38.227) 6.903,-38.182 SD.9 12.722,-38.205 15.091,-38.205 15.591,-38.705 v1(28.067,-38.705) ; v1(28.067,-46.355) 37.719,-46.355 46.101,-54.737 53.594,-54.737 54.236,-55.379 69.462,-55.379 v1(71.247,-53.594)
PB12: Pc.1 U1.33 | length 7.5
  Top Layer w0.22: U1.33 76.693,-42.022 79.756,-45.085
  Top Layer w0.5: 79.756,-45.085 Pc.1
PB13: Pc.2 U1.34 | length 10.2
  Top Layer w0.22: U1.34 77.209,-41.522 79.502,-43.815
  Top Layer w0.25: 79.502,-43.815 82.042,-43.815
  Top Layer w0.5: 82.042,-43.815 Pc.2
PB14: Pc.3 U1.35 | length 6.8
  Top Layer w0.22: U1.35 77.598,-41.022 79.121,-42.545
  Top Layer w0.5: 79.121,-42.545 Pc.3
PB15: Pc.4 U1.36 | length 9.6
  Top Layer w0.22: U1.36 78.114,-40.522 78.867,-41.275
  Top Layer w0.25: 78.867,-41.275 82.042,-41.275
  Top Layer w0.5: 82.042,-41.275 Pc.4
PC4: Pb.8 U1.24 | length 8
  Top Layer w0.22: 68.548,-50.197 68.636,-50.109 U1.24
  Top Layer w0.5: Pb.8 68.548,-50.197
PC5: Pb.9 U1.25 | length 5.2
  Top Layer w0.22: U1.25 69.136,-46.276 69.85,-46.99
  Top Layer w0.5: Pb.9 69.85,-46.99
PC6: Pc.5 U1.37 | length 6.2
  Top Layer w0.22: U1.37 78.85,-40.022
  Top Layer w0.5: 78.867,-40.005 Pc.5
PC7: Pc.6 U1.38 | length 9.6
  Top Layer w0.22: U1.38 77.953,-39.522 78.74,-38.735
  Top Layer w0.25: 78.74,-38.735 82.042,-38.735
  Top Layer w0.5: 82.042,-38.735 Pc.6
PC8: Pc.7 U1.39 | length 6.9
  Top Layer w0.22: U1.39 77.691,-39.022 79.248,-37.465
  Top Layer w0.5: 79.248,-37.465 Pc.7
PC9: Pc.8 U1.40 | length 10.2
  Top Layer w0.22: U1.40 77.302,-38.522 79.629,-36.195
  Top Layer w0.25: 79.629,-36.195 82.042,-36.195
  Top Layer w0.5: 82.042,-36.195 Pc.8
PC15: Pa.4 U1.4 | length 22.4
  Top Layer w0.22: 59.69,-31.115 60.325,-31.75 60.325,-35.186 61.161,-36.022 U1.4
  Top Layer w0.25: 46.609,-31.115 59.69,-31.115
  Top Layer w0.5: Pa.4 46.609,-31.115
PGND: BK_LCD.2 C11.1 C12.1 CE4.2 CE5.2 P2.1 P2.5 Pa.5 Pb.15 Pb.16 Q1.2 Q2.2 R5.1 R11.1 U3.1 | length 220.3
  Top Layer w0.8: P2.1 10.3,-1.281 10.864,-0.717 20.066,-0.717 20.46,-1.111 P2.5 v1@20.46,-8.121 ; v1(29.083,-8.128) 29.972,-9.017 v1@29.972,-14.297 ; R5.1 C12.1 34.493,-56.133 35.813,-56.133 36.605,-56.925 v1(38.989,-56.925) U3.1 ; v1(41.91,-33.655) v1(41.91,-14.725) Q2.2 ; v1(47.879,-14.725) 47.886,-14.725 51.307,-11.304 BK_LCD.2 ; C11.1 51.024,-56.134 v1(51.405,-56.515) ; v1(71.247,-56.485) 71.247,-58.381 71.794,-58.928 77.851,-58.928 78.232,-58.547 R11.1 79.785,-56.925 80.325,-57.465 Q1.2 ; Pb.16 Pb.15
  Top Layer w1: 38.481,-54.102 38.481,-55.372 38.989,-55.88 v1(38.989,-56.925)
  Bottom Layer w0.25: v1(41.91,-33.655) 46.609,-33.655
  Bottom Layer w0.8: v1(20.45,-8.121) 20.453,-8.124 29.08,-8.124 v1(29.083,-8.128) ; v1(29.972,-14.351) 38.862,-14.351 39.236,-14.725 v1(41.91,-14.725) ; CE5.2 37.465,-57.15 37.69,-56.925 v1(38.989,-56.925) 40.034,-56.925 40.386,-57.277 CE4.2@49.176,-57.277 ; v1@41.917,-14.725 v1(47.879,-14.725) ; 46.609,-33.655 Pa.5 50.256,-32.385 51.446,-33.575 54.946,-33.575 56.046,-34.675 56.046,-45.35 56.543,-45.847 76.293,-45.847 77.47,-47.024 Pb.15 ; CE4.2@49.376,-57.277 50.643,-57.277 v1(51.405,-56.515) ; v1@51.441,-56.509 71.223,-56.509 v1(71.247,-56.485) ; v1@71.247,-56.515 76.581,-56.515 77.47,-55.626 Pb.16
  Bottom Layer w1: CE4.2@49.176,-57.277 49.176,-57.25 CE4.2 ; CE4.2@49.276,-57.177 CE4.2@49.376,-57.277
RS: P2.4 Pb.7 U1.23 | length 108.2
  Top Layer w0.22: 67.31,-47.371 68.136,-46.545 U1.23
  Top Layer w0.5: v1(31.242,-5.595) 32.766,-7.119 32.766,-13.716 34.29,-15.24 v1(34.29,-45.205) ; v1(54.102,-50.927) 54.102,-53.34 v1(54.991,-54.229) ; Pb.7 67.31,-47.371
  Bottom Layer w0.25: 68.58,-53.721 68.58,-50.165
  Bottom Layer w0.5: 17.92,-4.995 18.52,-5.595 v1(31.242,-5.595) ; v1(34.29,-45.205) 38.22,-45.205 45.209,-52.194 52.835,-52.194 v1(54.102,-50.927) ; v1(54.991,-54.229) 68.072,-54.229 68.58,-53.721 ; Pb.7 68.58,-50.165
  Bottom Layer w0.8: 17.92,-4.995 P2.4
SD-CLK: Pb.5 SD.5 U1.21 | length 81.9
  Top Layer w0.22: 64.77,-47.879 67.136,-45.513 U1.21
  Top Layer w0.5: v1@17.646,-34.678 17.646,-40.252 19.05,-41.656 v1(19.05,-45.593) ; v1(56.261,-52.959) v1(56.261,-49.657) ; Pb.5 64.77,-47.879
  Bottom Layer w0.25: 66.04,-52.451 66.04,-50.165
  Bottom Layer w0.5: SD.5 14.097,-33.782 14.986,-34.671 v1(17.653,-34.671) ; v1(19.05,-45.593) 26.162,-45.593 27.813,-43.942 38.735,-43.942 45.974,-51.181 51.816,-51.181 53.34,-49.657 v1(56.261,-49.657) ; v1(56.261,-52.959) 56.265,-52.963 57.511,-52.963 57.761,-53.213 65.278,-53.213 66.04,-52.451 ; Pb.5 66.04,-50.165
SD-CS: Pb.4 R6.1 SD.2 U1.20 | length 88.7
  Top Layer w0.22: 63.5,-48.133 66.636,-44.997 U1.20
  Top Layer w0.25: 63.5,-50.165 63.5,-48.133
  Top Layer w0.5: R6.1 14.322,-27.276 14.986,-27.94 14.986,-30.422 v1(14.956,-30.452) ; v1(29.718,-42.672) v1(29.718,-30.48) ; v1(43.307,-46.609) 44.054,-47.356 57.35,-47.356 57.658,-47.664 57.658,-53.301 57.951,-53.594 61.849,-53.594 62.23,-53.213 Pb.4 63.5,-50.165
  Bottom Layer w0.5: SD.2 12.715,-30.467 14.941,-30.467 v1(14.956,-30.452) ; v1@14.986,-30.48 17.036,-30.48 17.043,-30.473 23.261,-30.473 23.268,-30.48 v1(29.718,-30.48) ; v1(29.718,-42.672) 39.37,-42.672 v1(43.307,-46.609)
SD-DI: Pd.9 SD.3 U1.57 | length 85.8
  Top Layer w0.22: 67.31,-26.543 68.631,-27.864 U1.57@68.631,-32.683
  Top Layer w0.5: v1(17.646,-31.623) 17.646,-24.01 v1(17.653,-24.003) ; v1(31.369,-24.003) 31.369,-22.479 33.02,-20.828 v1(33.02,-17.025) ; 67.31,-26.543 Pd.9
  Bottom Layer w0.25: 68.58,-22.733 68.58,-17.78
  Bottom Layer w0.5: SD.3 12.721,-31.602 17.626,-31.602 v1(17.646,-31.623) ; v1(17.653,-24.003) v1(31.369,-24.003) ; v1(33.02,-17.025) 33.027,-17.018 67.818,-17.018 68.58,-17.78 ; Pd.9 68.58,-22.733
SD-DO: Pd.8 SD.7 U1.56 | length 93.2
  Top Layer w0.22: 68.58,-26.924 69.131,-27.475 U1.56@69.131,-32.683
  Top Layer w0.25: 68.58,-26.924 68.58,-22.733
  Top Layer w0.5: v1(18.923,-35.941) v1(18.923,-25.4) ; v1(30.099,-25.4) 30.099,-21.971 31.623,-20.447 v1(31.623,-15.875) ; 68.58,-22.733 Pd.8
  Bottom Layer w0.5: SD.7 12.721,-35.962 18.903,-35.962 v1(18.923,-35.941) ; v1(18.923,-25.4) v1(30.099,-25.4) ; v1(31.623,-15.875) 68.58,-15.875 69.85,-17.145 Pd.8
SWCLK: P1.1 Pd.1 U1.49 | length 28.9
  Top Layer w0.22: U1.49@72.641,-32.674 72.641,-31.626 77.47,-26.797
  Top Layer w0.5: 77.47,-26.797 Pd.1
  Top Layer w0.8: Pd.1 79.121,-24.003 80.017,-23.107 P1.1
SWDIO: P1.2 Pc.14 U1.46 | length 39.3
  Top Layer w0.22: U1.46 76.083,-35.522 77.089,-34.516 77.089,-30.734 79.248,-28.575
  Top Layer w0.25: 79.248,-28.575 82.042,-28.575 Pc.14
  Top Layer w0.5: 82.617,-15.434 85.217,-18.034 85.217,-29.552 84.924,-29.845 Pc.14
  Top Layer w0.8: 82.617,-15.434 P1.2
V0: P2.3 R12.1 | length 46.4
  Top Layer w0.5: v1(30.353,-6.858) 31.5,-8.005 v1(31.5,-10.775) ; R12.1 53.725,-9.572 v1(53.725,-10.725)
  Bottom Layer w0.5: 15.375,-5.85 16.383,-6.858 v1(30.353,-6.858) ; v1@31.512,-10.763 31.525,-10.75 v1@53.725,-10.75
  Bottom Layer w0.8: 15.375,-5.85 P2.3@15.375,-2.6
V_BAT: D2.2 D3.2 Pa.1 U1.1 | length 59.2
  Top Layer w0.22: 59.055,-27.305 61.849,-30.099 61.849,-34.163 62.208,-34.522 U1.1
  Top Layer w0.5: Pa.1 59.055,-27.305
  Top Layer w0.8: D2.2 22.357,-34.784 24.017,-34.784 24.892,-33.909 ; v1(24.892,-26.797) 24.892,-33.909 ; D3.2@27.555,-34.784 D3.2 25.772,-34.789 24.892,-33.909
  Bottom Layer w0.8: v1(24.892,-26.797) 30.861,-26.797 32.385,-25.273 47.586,-25.273 47.879,-25.566 Pa.1
VDDA: C5.2 CE1.1 L1.1 Pa.13 POT1.1 R4.2 U1.13 U2.2 | length 93.2
  Top Layer w0.22: 50.165,-42.545 50.673,-43.053 59.478,-43.053 62.009,-40.522 U1.13 64.652,-40.522 64.897,-40.767 v1(65.786,-40.767)
  Top Layer w0.5: Pa.13 50.165,-42.545
  Top Layer w0.8: U2.2 4.953,-53.936 5.246,-54.229 R4.2@11.5,-54.229
  Bottom Layer w0.25: 42.545,-41.275 46.609,-41.275
  Bottom Layer w0.5: C5.2 63.373,-40.884 63.49,-40.767 v1(65.786,-40.767)
  Bottom Layer w0.8: U2.2 4.953,-49.022 7.483,-46.492 POT1.1 11.557,-44.196 14.515,-41.238 42.508,-41.238 42.545,-41.275 ; 46.609,-41.275 Pa.13 49.403,-42.545 49.911,-42.037 49.911,-38.989 50.292,-38.608 L1.1 CE1.1
pads on no net: M2.1 M3.1 M4.1 M5. P2.7 P2.8 P2.9 P2.10 Pa.7 Pd.12 SD. SD.1 SD.8

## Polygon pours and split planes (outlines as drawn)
GND on Bottom Layer "NONET_L-01_P-001" (solid, pour order 0): -0.05,0.05 98.25,0.05 98.25,-60.05 -0.05,-60.05
AGND on Top Layer "NONET_L-01_P-001" (solid, pour order 1): -0.05,0.05 98.25,0.05 98.25,-60.05 -0.05,-60.05

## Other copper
Top Layer:
  rectangle net AGND: 67.056,-39.497 70.358,-36.449
  rectangle net +3V3: 39.624,-54.356 46.355,-48.006
Bottom Layer:
  rectangle net +3V3: 33.274,-54.356 41.783,-51.435
  rectangle net GND: 66.829,-39.878 70.739,-35.941

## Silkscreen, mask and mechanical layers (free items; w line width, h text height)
Top Overlay:
  lines w0.1: 0,-58.25 1.75,-58.25 1.75,-60 ; 0,-1.75 1.75,-1.75 1.75,0 ; 96.45,-60 96.45,-58.25 98.2,-58.25 ; 96.45,0 96.45,-1.75 98.2,-1.75 ; 0,-60 98.2,-60 98.2,0 0,0 0,-60
  text "LCD" at 24.811,-6.304 h1.5
  text "Programmer" at 74.087,-12.408 h1.5
  text "OLED" at 4.745,-19.766 h1.5
  text "www.nekoorad.com" at 31.288,-20.02 h1.5
  text "09191143937" at 33.574,-22.179 h1.5
  text "STM32F334R8T6" at 61.509,-27.75 h1.3
  text "MicroBoard030603" at 60.706,-29.718 h1.3
  text "KEYs & LEDs" at 90.632,-41.61 h1.5 r90
Mechanical 1:
  the board outline again, w0.254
